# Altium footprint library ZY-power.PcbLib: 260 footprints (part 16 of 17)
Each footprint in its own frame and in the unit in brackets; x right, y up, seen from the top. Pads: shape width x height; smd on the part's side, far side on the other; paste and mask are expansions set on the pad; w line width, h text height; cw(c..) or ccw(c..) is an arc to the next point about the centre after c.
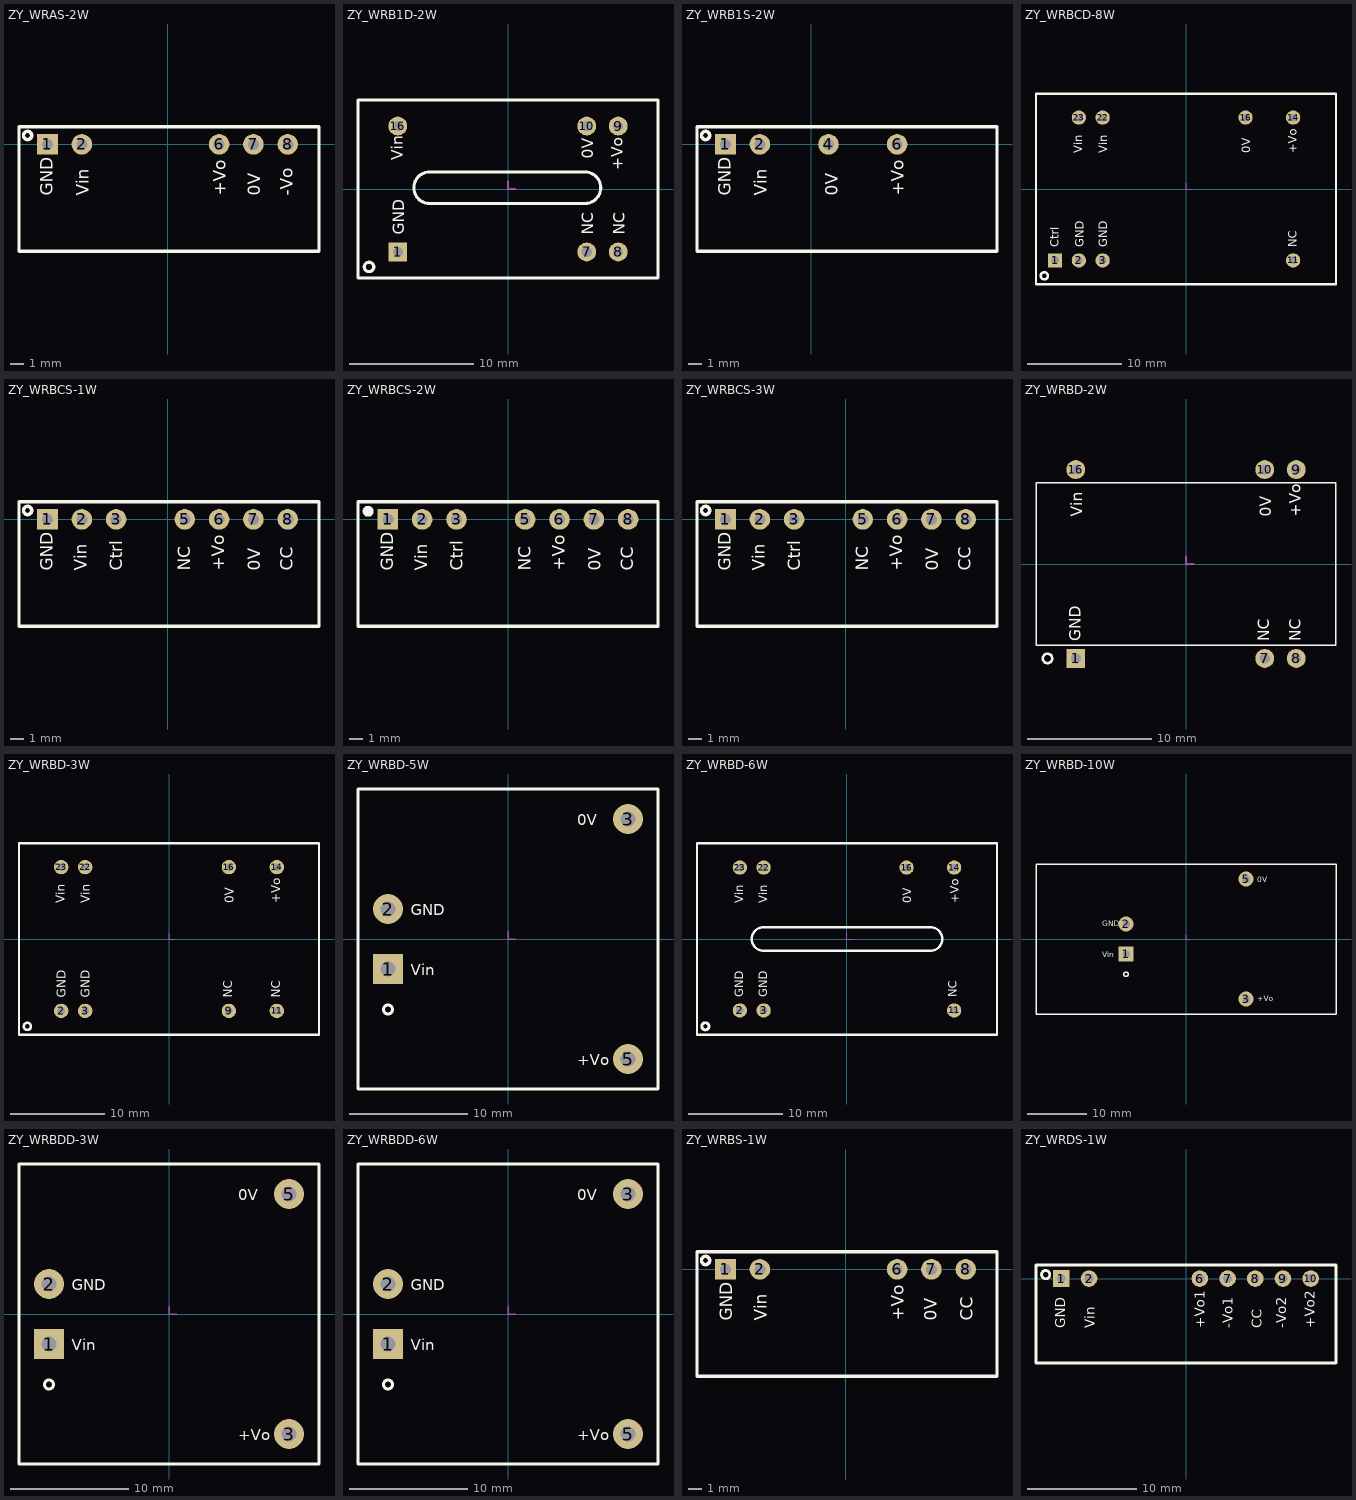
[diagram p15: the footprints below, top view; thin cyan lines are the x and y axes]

## ZY_WRAS-2W [mil]
height 480.31
pads (5):
  rect 60x60 hole 32: 1(-350,0)
  round 60 hole 32: 2(-250,0) 6(150,0) 7(250,0) 8(350,0)
Top Overlay:
  circle w10: c-408,26 r12
  lines w10: 441,-311 -433,-311 -433,51 441,51 441,-310
  text "GND" at -335,-149 h36
  text "Vin" at -230,-149 h36
  text "+Vo" at 170,-149 h36
  text "0V" at 270,-149 h36
  text "-Vo" at 365,-149 h36

## ZY_WRB1D-2W [mil]
height 326.77
pads (6):
  rect 60x60 hole 32: 1(-350,-200)
  round 60 hole 32: 7(250,-200) 8(350,-200) 9(350,200) 10(250,200) 16(-350,200)
Top Overlay:
  circle w10: c-441.38,-247.48 r15
  lines w9.65: -476.38,-282.48 -476.38,282.48 ; 476.38,-282.48 476.38,282.48
  lines w10: -476.38,-282.48 476.38,-282.48 ; -476.38,282.48 476.38,282.48 ; -299,4 cw(c-249,4) -249,54 244.56,54 cw(c244.56,4) 294.56,4 cw(c244.56,4) 244.56,-46 -249,-46 cw(c-249,4) -299,4
  text "NC" at 370,-145 h36
  text "GND" at -330,-145 h36
  text "Vin" at -335,91.71 h36
  text "0V" at 270,96.33 h36
  text "+Vo" at 365,60 h36
  text "NC" at 270,-145 h36
Mechanical 15:
  lines w5: 0,25 0,0 25,0

## ZY_WRB1S-2W [mil]
height 480.31
pads (4):
  rect 60x60 hole 32: 1(-250,0)
  round 60 hole 32: 2(-150,0) 4(50,0) 6(250,0)
Top Overlay:
  circle w10: c-308,26 r12
  lines w10: 541,-311 -333,-311 -333,51 541,51 541,-310
  text "0V" at 77,-150 h36
  text "+Vo" at 270,-150 h36
  text "Vin" at -130,-150 h36
  text "GND" at -235,-150 h36

## ZY_WRBCD-8W [mil]
pads (8):
  rect 60x60 hole 32: 1(-550,-300)
  round 60 hole 32: 2(-450,-300) 3(-350,-300) 11(450,-300) 14(450,300) 16(250,300) 22(-350,300) 23(-450,300)
Top Overlay:
  circle w10: c-594.92,-364.61 r15
  lines w10: -629.92,-399.61 -629.92,399.61 629.92,399.61 629.92,-399.61 -629.92,-399.61
  text "GND" at -430,-245 h36
  text "GND" at -330,-245 h36
  text "NC" at 465,-245 h36
  text "+Vo" at 465,150 h36
  text "0V" at 270,150 h36
  text "Vin" at -330,150 h36
  text "Vin" at -435,150 h36
  text "Ctrl" at -535,-245 h36
Mechanical 15:
  lines w5: 0,25 0,0 25,0

## ZY_WRBCS-1W [mil]
height 480.31
pads (7):
  rect 60x60 hole 32: 1(-350,0)
  round 60 hole 32: 2(-250,0) 3(-150,0) 5(50,0) 6(150,0) 7(250,0) 8(350,0)
Top Overlay:
  circle w10: c-408,26 r12
  lines w10: 441,-311 -433,-311 -433,51 441,51 441,-310
  text "NC" at 66,-150 h36
  text "Ctrl" at -132,-150 h36
  text "GND" at -335,-150 h36
  text "Vin" at -235,-150 h36
  text "+Vo" at 165,-150 h36
  text "0V" at 270,-150 h36
  text "CC" at 365,-150 h36

## ZY_WRBCS-2W [mil]
pads (7):
  rect 60x60 hole 32: 1(-350,0)
  round 60 hole 32: 2(-250,0) 3(-150,0) 5(50,0) 6(150,0) 7(250,0) 8(350,0)
Top Overlay:
  circle w15.75: c-407.48,23.62 r7.87
  lines w10: 436.99,-311.02 437.01,-311.01 ; 436.99,-311.02 -437.01,-311.02 -437.01,51.18 437.01,51.18 437.01,-311.01
  text "CC" at 365,-150 h36
  text "0V" at 270,-150 h36
  text "+Vo" at 165,-150 h36
  text "Vin" at -235,-150 h36
  text "GND" at -335,-150 h36
  text "Ctrl" at -132,-150 h36
  text "NC" at 66,-150 h36

## ZY_WRBCS-3W [mil]
pads (7):
  rect 60x60 hole 32: 1(-350,0)
  round 60 hole 32: 2(-250,0) 3(-150,0) 5(50,0) 6(150,0) 7(250,0) 8(350,0)
Top Overlay:
  circle w10: c-408,26 r12
  lines w10: 441,-311 -433,-311 -433,51 441,51 441,-310
  text "NC" at 66,-150 h36
  text "Ctrl" at -132,-150 h36
  text "CC" at 365,-150 h36
  text "0V" at 270,-150 h36
  text "+Vo" at 165,-150 h36
  text "Vin" at -235,-150 h36
  text "GND" at -335,-150 h36

## ZY_WRBD-2W [mil]
pads (6):
  rect 60x60 hole 32: 1(-350,-300)
  round 60 hole 32: 7(250,-300) 8(350,-300) 9(350,300) 10(250,300) 16(-350,300)
Top Overlay:
  circle w8: c-440,-300 r15
  lines w4: -476.38,-257.48 -476.38,257.48 476.38,257.48 476.38,-257.48 -476.38,-257.48
  text "GND" at -335,-245 h36
  text "Vin" at -330,150 h36
  text "NC" at 265,-245 h36
  text "NC" at 365,-245 h36
  text "+Vo" at 365,150 h36
  text "0V" at 270,150 h36
Mechanical 15:
  lines w5: 0,25 0,0 25,0

## ZY_WRBD-3W [mil] "宽压输入隔离稳压单输出电源模块"
height 374.02
pads (8):
  round 60 hole 32: 2(-450,-300) 3(-350,-300) 9(250,-300) 11(450,-300) 14(450,300) 16(250,300) 22(-350,300) 23(-450,300)
Top Overlay:
  circle w10: c-590.98,-364.61 r15
  lines w10: -625.98,-399.61 -625.98,399.61 625.98,399.61 625.98,-399.61 -550,-399.61 -551.38,-399.61 -625.98,-399.61
  text "GND" at -430,-245 h36
  text "GND" at -330,-245 h36
  text "NC" at 265,-245 h36
  text "NC" at 465,-245 h36
  text "+Vo" at 465,150 h36
  text "0V" at 270,150 h36
  text "Vin" at -330,150 h36
  text "Vin" at -435,150 h36
Mechanical 15:
  lines w5: 0,25 0,0 25,0

## ZY_WRBD-5W [mil]
height 460.63
pads (4):
  rect 100x100 hole 50: 1(-400,-100)
  round 100 hole 50: 2(-400,100) 3(400,400) 5(400,-400)
Top Overlay:
  circle w10: c-400,-235 r15
  lines w10: -500,-500 500,-500 500,500 -500,500 -500,-500
  text "GND" at -325,80 h36
  text "Vin" at -325,-120 h36
  text "+Vo" at 230,-420 h36
  text "0V" at 230,380 h36
Mechanical 15:
  lines w5: 0,25 0,0 25,0

## ZY_WRBD-6W [mil]
height 413.39
pads (7):
  round 60 hole 32: 2(-450,-300) 3(-350,-300) 11(450,-300) 14(450,300) 16(250,300) 22(-350,300) 23(-450,300)
Top Overlay:
  circle w12: c-594.92,-366.57 r15
  lines w10: -629.92,-401.57 629.92,-401.57 629.92,401.57 -629.92,401.57 -629.92,-401.57 ; -400,0 cw(c-350,0) -350,50 350,50 cw(c350,0) 400,0 cw(c350,0) 350,-50 -350,-50 cw(c-350,0) -400,0
  text "0V" at 270,150 h36
  text "+Vo" at 470,150 h36
  text "NC" at 460,-245 h36
  text "Vin" at -335,150 h36
  text "Vin" at -435,150 h36
  text "GND" at -335,-245 h36
  text "GND" at -435,-245 h36
Mechanical 15:
  lines w5: 0,25 0,0 25,0

## ZY_WRBD-10W [mil]
pads (4):
  rect 100x100 hole 50: 1(-400,-100)
  round 100 hole 50: 2(-400,100) 3(400,-400) 5(400,400)
Top Overlay:
  circle w10: c-400,-235 r15
  lines w10: -1000,-500 1000,-500 1000,500 -1000,500 -1000,-500
  text "Vin" at -560,-120 h36
  text "GND" at -560,85 h36
  text "0V" at 475,380 h36
  text "+Vo" at 475,-415 h36
Mechanical 15:
  lines w5: 0,25 0,0 25,0

## ZY_WRBDD-3W [mil]
height 460.63
pads (4):
  rect 100x100 hole 50: 1(-400,-100)
  round 100 hole 50: 2(-400,100) 3(400,-400) 5(400,400)
Top Overlay:
  circle w10: c-400,-235 r15
  lines w10: -500,-500 -500,500 500,500 500,-500 -500,-500
  text "GND" at -325,80 h36
  text "Vin" at -325,-120 h36
  text "+Vo" at 230,-420 h36
  text "0V" at 230,380 h36
Mechanical 15:
  lines w5: 0,25 0,0 25,0

## ZY_WRBDD-6W [mil]
height 460.63
pads (4):
  rect 100x100 hole 50: 1(-400,-100)
  round 100 hole 50: 2(-400,100) 3(400,400) 5(400,-400)
Top Overlay:
  circle w10: c-400,-235 r15
  lines w10: -500,-500 -500,500 500,500 500,-500 -500,-500
  text "GND" at -325,80 h36
  text "Vin" at -325,-120 h36
  text "+Vo" at 230,-420 h36
  text "0V" at 230,380 h36
Mechanical 15:
  lines w5: 0,25 0,0 25,0

## ZY_WRBS-1W [mil]
pads (5):
  rect 60x60 hole 32: 1(-350,0)
  round 60 hole 32: 2(-250,0) 6(150,0) 7(250,0) 8(350,0)
Top Overlay:
  circle w10: c-408,26 r12
  lines w10: 441,-311 -433,-311 -433,51 441,51 441,-310
  text "CC" at 370,-150 h36
  text "0V" at 265,-150 h36
  text "+Vo" at 170,-150 h36
  text "Vin" at -230,-150 h36
  text "GND" at -330,-150 h36

## ZY_WRDS-1W [mil]
height 452.76
pads (7):
  rect 60x60 hole 32: 1(-450,0)
  round 60 hole 32: 2(-350,0) 6(50,0) 7(150,0) 8(250,0) 9(350,0) 10(450,0)
Top Overlay:
  circle w10: c-506.34,14.21 r15
  lines w10: -541.34,-305.12 -541.34,49.21 541.34,49.21 541.34,-305.12 -541.34,-305.12
  text "-Vo2" at 362,-180 h36
  text "+Vo2" at 465,-180 h36
  text "CC" at 274,-180 h36
  text "GND" at -435,-180 h36
  text "Vin" at -330,-180 h36
  text "+Vo1" at 67,-180 h36
  text "-Vo1" at 168,-180 h36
